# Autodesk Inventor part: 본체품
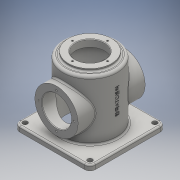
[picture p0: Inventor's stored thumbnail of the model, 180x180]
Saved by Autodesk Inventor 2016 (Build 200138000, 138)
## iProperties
Created: 2019-08
Part Number: 본체품
Material: 일반
Document SubType Name: Modeling
Designer: user
Density: 1 g/cm^3
Appearance: 기본값
Author: user
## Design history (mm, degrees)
node "작업 평면2"
sketch "스케치3"
  geometry: L1 (-70, 70)-(70, 70); L2 (70, 70)-(70, -70); L3 (70, -70)-(-70, -70); L4 (-70, -70)-(-70, 70); L5 (-70, 70)-(70, -70); L6 (70, 70)-(-70, -70); 1 further point
  constraints: 12 end point, 2 midpoint, 2 parallel, 1 horizontal, 1 perpendicular
  dimensions: "d8" = 140 distance of L1.start L1.end; "d9" = 140 distance of L1.end L2.end
extrude "돌출2" new body sketch "스케치3" distance "d10" = 10; taper "d11" = 0 deg
fillet "모깎기2" dims "d12" = 10
sketch "스케치4"
  geometry: C1 r 50 at (0, 0); 1 further point
  constraints: 1 centre point, 1 coincident
  dimensions: "d13" = 100 diameter of C1
extrude "돌출3" join sketch "스케치4" distance "d14" = 110; taper "d15" = 0 deg
sketch "스케치8"
  geometry: C1 r 40 at (0, 0); 1 further point
  constraints: 1 centre point, 1 coincident
  dimensions: "d42" = 80 diameter of C1
extrude "돌출6" join sketch "스케치8" stored distance "d43" = 124; taper "d44" = 0 deg
sketch "스케치5"
  geometry: C1 r 40 at (0, 0); 1 further point
  constraints: 1 centre point, 1 coincident
  dimensions: "d16" = 80 diameter of C1
extrude "돌출4" join sketch "스케치5" distance "d17" = 5; taper "d18" = 0 deg
sketch "스케치6"
  geometry: C1 r 45 at (0, 0); 1 further point
  constraints: 1 centre point, 1 coincident
  dimensions: "d19" = 90 diameter of C1
extrude "돌출5" cut sketch "스케치6" distance "d20" = 112; taper "d21" = 0 deg
hole "구멍1" diameter "d24" = 54; stored, may be unused: countersink angle "d28" = 90 deg, drill point angle "d30" = 118 deg; dims "d22" = 10, "d23" = 10, "d25" = 6, "d26" = 4, "d27" = 2, "d29" = 8
sketch "스케치7" dims "d31" = 65
  geometry: 3 further points
  constraints: 2 horizontal alignment, 1 coincident, 2 other
hole "구멍2" sketch "스케치7" at (32.5, 0) diameter "d32" = 3.242; stored, may be unused: countersink angle "d36" = 90 deg, drill point angle "d38" = 118 deg; dims "d33" = 8, "d34" = 4, "d35" = 2, "d37" = 10
sketch "스케치9"
  geometry: C1 r 27 at (0, 0); 1 further point
  constraints: 1 centre point, 1 coincident
  dimensions: "d45" = 54 diameter of C1
extrude "돌출7" cut sketch "스케치9" stored distance "d46" = 124; taper "d47" = 0 deg
sketch "스케치10" dims "d48" = 65
  geometry: 3 further points
  constraints: 2 horizontal alignment, 1 coincident, 2 other
hole "구멍3" sketch "스케치10" at (32.5, 0) diameter "d49" = 3.242; stored, may be unused: countersink angle "d53" = 90 deg, drill point angle "d55" = 118 deg; dims "d50" = 8, "d51" = 4, "d52" = 2, "d54" = 10
hole "구멍4" diameter "d64" = 9; stored, may be unused: countersink angle "d68" = 90 deg, drill point angle "d70" = 118 deg; dims "d65" = 9, "d66" = 4, "d67" = 2, "d69" = 9, "d71" = 10, "d72" = 10
hole "구멍5" diameter "d75" = 9; stored, may be unused: countersink angle "d79" = 90 deg, drill point angle "d81" = 118 deg; dims "d73" = 10, "d74" = 10, "d76" = 6, "d77" = 4, "d78" = 2, "d80" = 8
fillet "모깎기3" dims "d82" = 5
fillet "모깎기4" dims "d83" = 3
fillet "모깎기5" dims "d84" = 3
fillet "모깎기6" dims "d85" = 3
fillet "모깎기7" dims "d86" = 3
chamfer "모따기1" distance "d87" = 1; stored, may be unused: second distance "d88" = 2, angle "d89" = 45 deg
chamfer "모따기2" distance "d90" = 1; stored, may be unused: second distance "d91" = 2, angle "d92" = 45 deg
chamfer "모따기3" distance "d93" = 1; stored, may be unused: second distance "d94" = 2, angle "d95" = 45 deg
fillet "모깎기8" dims "d96" = 3
node "작업 평면3"
sketch "스케치11"
  geometry: L1 (60, -60)-(-60, -60) reference; 2 further points
  constraints: 1 vertical alignment, 1 other
  dimensions: "d98" = 70 distance from line of L1 point (0, 10)
feature "엠보싱1" sketch "스케치11" dims "d16" = 80, "d99" = 0.5, "d100" = 0
node "솔리드2"
pattern_circular "원형 패턴1" dims angle "d40" = 360 deg
pattern_circular "원형 패턴2" dims angle "d57" = 360 deg
mirror "대칭1"
pattern_circular "원형 패턴3" dims angle "d60" = 360 deg
mirror "대칭2"
